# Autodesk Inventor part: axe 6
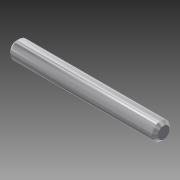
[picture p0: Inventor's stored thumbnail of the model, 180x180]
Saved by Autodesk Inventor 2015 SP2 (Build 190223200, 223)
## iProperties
Created: 2015-08
Part Number: axe 6
Material: Générique
Document SubType Name: Modeling
Designer: Dominique
Density: 1 g/cm^3
Appearance: Aluminum - Poli
Author: Dominique
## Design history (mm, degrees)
sketch "Esquisse1"
  geometry: L1 (0, 0)-(50, 0); L2 (50, 0)-(50, 2); L3 (49, 3)-(1, 3); L4 (0, 2)-(0, 0); L5 (0, 2)-(1, 3); L6 (49, 3)-(50, 2); 2 further points
  constraints: 12 end point, 4 point on line, 2 parallel, 1 horizontal, 1 perpendicular
  dimensions: "d0" = 50 distance of point (0, 3) point (50, 3); "d1" = 3 distance of point (50, 3) L1.end; "d2" = 1 distance of L4.start point (0, 3); "d3" = 1 distance of L3.end point (0, 3) (= d2); "d4" = 1 distance of L3.start point (50, 3) (= d2); "d5" = 1 distance of L2.end point (50, 3) (= d4)
revolve "Révolution1" sketch "Esquisse1" stored, may be unused: angle "d6" = 90 deg
node "Solide1"
